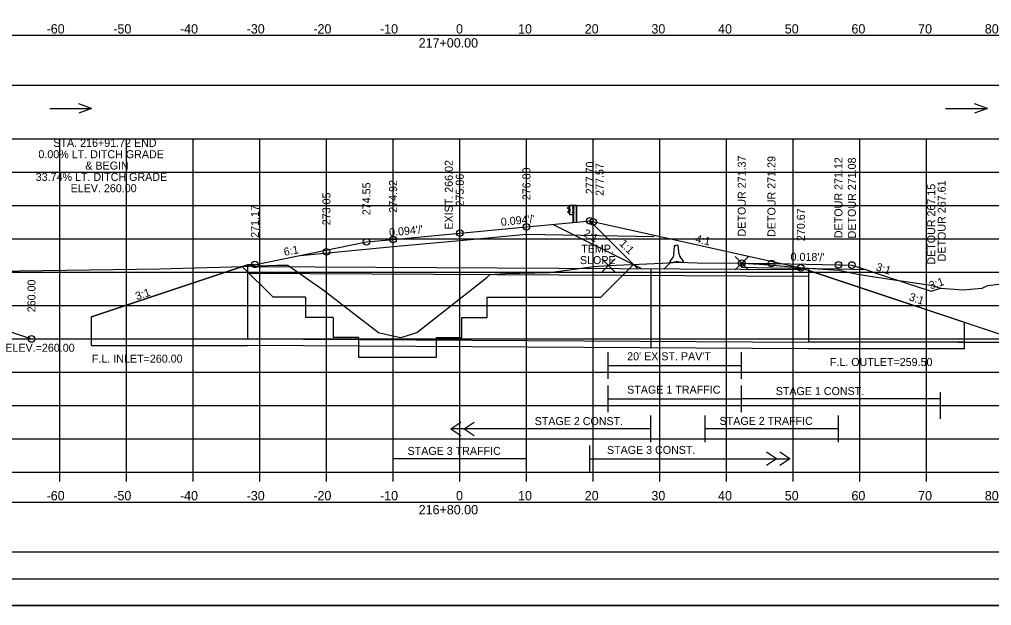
# Model space of a CAD drawing. Extents: x 4667 to 1632277, y -2100 to 724501.
# Drawn here: x 5711.1 to 5856.9, y -1323.8 to -1235.9 of the extents above; entities that cross this region are included whole.
import ezdxf

# ---------------------------------------------------------------- set-up
doc = ezdxf.new("R2010")
doc.units = 0
for name, color, linetype in [('R_Alt Surface', 7, 'Continuous'), ('R_Axis', 7, 'Continuous'), ('R_Axis Annot', 7, 'Continuous'), ('R_Border', 7, 'Continuous'), ('R_Border Notes', 7, 'Continuous'), ('R_Detour', 7, 'Continuous'), ('R_Detour Annot', 7, 'Continuous'), ('R_Draft', 7, 'Continuous'), ('R_Exist Surface', 7, 'Continuous'), ('R_Fin Surface', 7, 'Continuous'), ('R_Fin Surface Annot', 7, 'Continuous'), ('R_Grid', 7, 'Continuous'), ('R_MOT', 7, 'Continuous'), ('R_No Plot', 7, 'Continuous'), ('R_Proposed CofA', 7, 'Continuous'), ('R_ROW', 7, 'Continuous'), ('R_Striping', 7, 'Continuous'), ('R_Temp Easement', 7, 'Continuous'), ('R_Water', 7, 'Continuous'), ('R_Water Annot', 7, 'Continuous'), ('T_Drafting', 7, 'Continuous')]:
    doc.layers.add(name, color=color, linetype=linetype)

msp = doc.modelspace()

# ---------------------------------------------------------------- linework, layer by layer
at = {"layer": 'R_Alt Surface'}
msp.add_line((5805.83, -1273.23), (5805.83, -1285.1), dxfattribs=at)
msp.add_lwpolyline([(5753.27, -1271.24), (5767.18, -1269.93), (5777.18, -1268.99), (5787.18, -1268.05), (5806.34, -1268.43)], dxfattribs=at)
at = {"layer": 'R_Axis'}
for p, q in [((5667.18, -1303.77), (5947.18, -1303.77)), ((5717.18, -1305.17), (5717.18, -1303.77)), ((5727.18, -1305.17), (5727.18, -1303.77)), ((5737.18, -1305.17), (5737.18, -1303.77)), ((5747.18, -1305.17), (5747.18, -1303.77)), ((5757.18, -1305.17), (5757.18, -1303.77)), ((5767.18, -1305.17), (5767.18, -1303.77)), ((5777.18, -1305.17), (5777.18, -1303.77)), ((5787.18, -1305.17), (5787.18, -1303.77)), ((5797.18, -1305.17), (5797.18, -1303.77)), ((5807.18, -1305.17), (5807.18, -1303.77)), ((5817.18, -1305.17), (5817.18, -1303.77)), ((5827.18, -1305.17), (5827.18, -1303.77)), ((5837.18, -1305.17), (5837.18, -1303.77)), ((5847.18, -1305.17), (5847.18, -1303.77))]:
    msp.add_line(p, q, dxfattribs=at)
at = {"layer": 'R_Border'}
msp.add_line((5964.36, -1319.77), (5648.18, -1319.77), dxfattribs=at)
at = {"layer": 'R_Detour'}
msp.add_line((5847.89, -1276.62), (5849.29, -1276.15), dxfattribs=at)
for points in [[(5838.11, -1273.39), (5833.97, -1273.32), (5823.92, -1273.14), (5819.46, -1273.06), (5819.46, -1272.4)], [(5819.46, -1272.4), (5819.86, -1272.4), (5822.46, -1272.45), (5823.83, -1272.47), (5823.92, -1272.47), (5824.26, -1272.48), (5833.97, -1272.65), (5834.42, -1272.66), (5835.98, -1272.69), (5838.24, -1273.43), (5839.18, -1273.75), (5840.84, -1274.29), (5844.01, -1275.34), (5847.89, -1276.62)]]:
    msp.add_lwpolyline(points, dxfattribs=at)
at = {"layer": 'R_Draft'}
for p, q in [((5793.52, -1263.96), (5793.63, -1263.9)), ((5793.53, -1263.98), (5793.62, -1263.93)), ((5793.66, -1265.11), (5793.66, -1263.75)), ((5794.16, -1263.74), (5794.17, -1263.74)), ((5794.16, -1263.74), (5794.23, -1263.75)), ((5794.19, -1266.26), (5794.19, -1263.74)), ((5794.65, -1263.75), (5794.65, -1266.26)), ((5794.68, -1263.75), (5794.68, -1266.26)), ((5793.51, -1264.91), (5793.38, -1264.8)), ((5793.39, -1264.06), (5793.52, -1263.96)), ((5793.56, -1264.31), (5793.39, -1264.21)), ((5793.4, -1264.08), (5793.53, -1263.98)), ((5793.57, -1264.29), (5793.4, -1264.19)), ((5793.52, -1264.89), (5793.4, -1264.79)), ((5793.41, -1264.64), (5793.57, -1264.55)), ((5793.42, -1264.66), (5793.58, -1264.57)), ((5793.62, -1264.97), (5793.51, -1264.91)), ((5793.63, -1264.95), (5793.52, -1264.89)), ((5793.6, -1264.49), (5793.6, -1264.36)), ((5793.62, -1264.49), (5793.62, -1264.36)), ((5793.67, -1264.49), (5793.67, -1264.37)), ((5793.67, -1264.37), (5793.72, -1264.37)), ((5793.67, -1264.4), (5793.72, -1264.4)), ((5793.67, -1264.46), (5793.72, -1264.46)), ((5793.67, -1264.46), (5793.72, -1264.46)), ((5793.67, -1264.49), (5793.72, -1264.49)), ((5793.73, -1264.48), (5793.73, -1264.38)), ((5794.15, -1264.05), (5794.1, -1264.05)), ((5794.1, -1264.05), (5794.1, -1264.18)), ((5794.1, -1264.11), (5794.16, -1264.11)), ((5794.15, -1264.18), (5794.1, -1264.18)), ((5794.1, -1264.86), (5794.1, -1264.74)), ((5794.1, -1264.74), (5794.15, -1264.74)), ((5794.1, -1264.8), (5794.16, -1264.8)), ((5794.1, -1264.86), (5794.15, -1264.86)), ((5794.16, -1265.11), (5794.19, -1265.11)), ((5794.23, -1264.17), (5794.23, -1264.05)), ((5794.23, -1264.05), (5794.28, -1264.05)), ((5794.23, -1264.08), (5794.28, -1264.08)), ((5794.23, -1264.14), (5794.27, -1264.14)), ((5794.23, -1264.14), (5794.28, -1264.14)), ((5794.23, -1264.17), (5794.28, -1264.17)), ((5794.24, -1264.86), (5794.24, -1264.74)), ((5794.24, -1264.74), (5794.29, -1264.74)), ((5794.24, -1264.77), (5794.29, -1264.77)), ((5794.24, -1264.83), (5794.28, -1264.83)), ((5794.24, -1264.83), (5794.29, -1264.83)), ((5794.24, -1264.86), (5794.29, -1264.86)), ((5794.28, -1264.16), (5794.28, -1264.06)), ((5794.29, -1264.85), (5794.29, -1264.75))]:
    msp.add_line(p, q, dxfattribs=at)
for points in [[(5793.63, -1263.74), (5793.64, -1265.11), (5794.16, -1265.11), (5794.16, -1263.74)], [(5793.67, -1264.35), (5793.67, -1264.52), (5793.66, -1264.52), (5793.66, -1264.35)], [(5793.73, -1264.4), (5793.73, -1264.46), (5793.76, -1264.46), (5793.76, -1264.4)], [(5794.1, -1264.05), (5794.1, -1264.18), (5794.16, -1264.18), (5794.16, -1264.05)], [(5794.1, -1264.74), (5794.1, -1264.86), (5794.16, -1264.86), (5794.16, -1264.74)], [(5794.23, -1264.03), (5794.23, -1264.19), (5794.22, -1264.19), (5794.22, -1264.03)], [(5794.24, -1264.72), (5794.24, -1264.88), (5794.23, -1264.88), (5794.23, -1264.72)], [(5794.29, -1264.08), (5794.29, -1264.14), (5794.31, -1264.14), (5794.31, -1264.08)], [(5794.3, -1264.77), (5794.3, -1264.83), (5794.32, -1264.83), (5794.32, -1264.77)]]:
    msp.add_lwpolyline(points, close=True, dxfattribs=at)
msp.add_lwpolyline([(5794.68, -1263.75), (5794.23, -1263.75), (5794.23, -1266.26)], dxfattribs=at)
for centre, radius, start, end in [((5793.43, -1264.13), 0.0856, 122.0217, 240.7501), ((5793.47, -1264.74), 0.109, 120.88, 214.7816), ((5793.43, -1264.13), 0.062, 122.0217, 240.7501), ((5793.47, -1264.74), 0.0854, 120.88, 214.7816), ((5793.53, -1264.37), 0.0622, 4.9556, 61.894), ((5793.6, -1264.43), 0.0453, 93.9303, 257.0446), ((5793.53, -1264.37), 0.0865, 4.9556, 61.894), ((5793.55, -1264.5), 0.0462, 293.1464, 8.2196), ((5793.55, -1264.5), 0.0703, 293.1464, 8.2196), ((5793.71, -1264.38), 0.022, 317.7756, 45.4255), ((5793.64, -1264.43), 0.0922, 339.7423, 20.2577), ((5793.7, -1264.48), 0.025, 323.3766, 39.0666), ((5794.26, -1264.06), 0.022, 317.7756, 45.4255), ((5794.19, -1264.11), 0.0922, 339.7423, 20.2577), ((5794.26, -1264.16), 0.025, 323.3766, 39.0666), ((5794.27, -1264.75), 0.022, 317.7756, 45.4255), ((5794.2, -1264.8), 0.0922, 339.7423, 20.2577), ((5794.27, -1264.85), 0.025, 323.3766, 39.0666)]:
    msp.add_arc(centre, radius, start, end, dxfattribs=at)
at = {"layer": 'R_Exist Surface'}
msp.add_lwpolyline([(5693.57, -1273.8), (5732.18, -1273.26), (5733.86, -1273.21), (5742.97, -1272.97), (5749.72, -1272.7), (5751.4, -1272.69), (5756.7, -1276.4), (5764.98, -1282.78), (5766.89, -1283.26), (5768.33, -1283.53), (5769.98, -1283.04), (5770.75, -1282.8), (5781.22, -1274.57), (5781.72, -1274.1), (5783.99, -1273.95), (5790.64, -1273.82), (5797.3, -1272.92), (5797.99, -1272.85), (5799.47, -1272.78), (5807.54, -1272.42), (5809.96, -1272.27), (5812.79, -1272.34), (5819.46, -1272.4), (5822.13, -1272.55), (5823.49, -1272.66), (5829.32, -1273.18), (5834.02, -1273.45), (5837.11, -1274.09), (5841.33, -1274.74), (5847.83, -1275.69), (5849.32, -1276.17), (5852.6, -1276.41), (5855.53, -1276.17), (5856.38, -1275.76), (5862.08, -1275.08)], dxfattribs=at)
at = {"layer": 'R_Fin Surface'}
for points in [[(5683.37, -1273.91), (5712.95, -1283.77), (5721.97, -1283.77), (5721.97, -1280.44), (5745.35, -1272.64), (5746.35, -1272.64), (5763.18, -1269.22), (5767.18, -1268.85), (5777.18, -1267.91), (5787.18, -1266.97), (5794.68, -1266.26), (5796.68, -1266.07)], [(5851.85, -1284.27), (5861.84, -1284.27), (5896.84, -1284.27), (5928.43, -1273.74)]]:
    msp.add_lwpolyline(points, dxfattribs=at)
at = {"layer": 'R_Grid'}
for p, q in [((5667.18, -1253.77), (5947.18, -1253.77)), ((5717.18, -1303.77), (5717.18, -1253.77)), ((5727.18, -1303.77), (5727.18, -1253.77)), ((5737.18, -1303.77), (5737.18, -1253.77)), ((5747.18, -1303.77), (5747.18, -1253.77)), ((5757.18, -1303.77), (5757.18, -1253.77)), ((5767.18, -1303.77), (5767.18, -1253.77)), ((5777.18, -1303.77), (5777.18, -1253.77)), ((5787.18, -1303.77), (5787.18, -1253.77)), ((5797.18, -1303.77), (5797.18, -1253.77)), ((5807.18, -1303.77), (5807.18, -1253.77)), ((5817.18, -1303.77), (5817.18, -1253.77)), ((5827.18, -1303.77), (5827.18, -1253.77)), ((5837.18, -1303.77), (5837.18, -1253.77)), ((5847.18, -1303.77), (5847.18, -1253.77)), ((5667.18, -1258.77), (5947.18, -1258.77)), ((5667.18, -1263.77), (5947.18, -1263.77)), ((5667.18, -1268.77), (5947.18, -1268.77)), ((5667.18, -1273.77), (5947.18, -1273.77)), ((5667.18, -1278.77), (5947.18, -1278.77)), ((5667.18, -1283.77), (5947.18, -1283.77)), ((5667.18, -1288.77), (5947.18, -1288.77)), ((5667.18, -1293.77), (5947.18, -1293.77)), ((5667.18, -1298.77), (5947.18, -1298.77)), ((5667.18, -1303.77), (5947.18, -1303.77))]:
    msp.add_line(p, q, dxfattribs=at)
at = {"layer": 'R_MOT'}
for p, q in [((5809.46, -1269.74), (5809.65, -1269.74)), ((5809.84, -1269.73), (5809.65, -1269.74)), ((5809.3, -1271.12), (5809.4, -1269.8)), ((5810.08, -1271.09), (5809.91, -1269.78)), ((5808.72, -1272.18), (5809.16, -1271.51)), ((5808.73, -1272.35), (5808.72, -1272.18)), ((5809.23, -1272.33), (5808.73, -1272.35)), ((5809.72, -1272.15), (5809.23, -1272.33)), ((5810.23, -1272.3), (5809.72, -1272.15)), ((5810.73, -1272.29), (5810.23, -1272.3)), ((5810.72, -1272.12), (5810.24, -1271.48)), ((5810.73, -1272.29), (5810.72, -1272.12))]:
    msp.add_line(p, q, dxfattribs=at)
for centre, radius, start, end in [((5809.46, -1269.8), 0.0625, 91.6884, 175.6794), ((5809.85, -1269.79), 0.0625, 7.6974, 91.6884), ((5808.47, -1271.05), 0.833, 326.6964, 355.6794), ((5810.91, -1270.98), 0.833, 187.6974, 216.6804)]:
    msp.add_arc(centre, radius, start, end, dxfattribs=at)
at = {"layer": 'R_No Plot'}
for p, q in [((5791.18, -1266.59), (5804.45, -1273.22)), ((5635.78, -1323.75), (5969.12, -1323.75))]:
    msp.add_line(p, q, dxfattribs=at)
for points in [[(5635.78, -1110.41), (5969.12, -1110.41), (5969.12, -1323.75), (5635.78, -1323.75)], [(5882.1, -1114.31), (5901.72, -1114.31), (5901.72, -1124.19), (5917.84, -1124.19), (5941.04, -1124.19), (5941.04, -1148.52), (5964.36, -1148.52), (5964.36, -1319.77), (5648.18, -1319.77), (5648.18, -1114.31)]]:
    msp.add_lwpolyline(points, close=True, dxfattribs=at)
for points in [[(5799.47, -1272.78), (5798.47, -1271.78), (5799.47, -1272.78), (5798.47, -1273.78), (5799.47, -1272.78), (5800.47, -1273.78), (5799.47, -1272.78), (5800.47, -1271.78)], [(5819.46, -1272.4), (5818.46, -1271.4), (5819.46, -1272.4), (5818.46, -1273.4), (5819.46, -1272.4), (5820.46, -1273.4), (5819.46, -1272.4), (5820.46, -1271.4)]]:
    msp.add_lwpolyline(points, dxfattribs=at)
for centre in [(5787.18, -1266.97), (5796.68, -1266.07), (5797.18, -1266.2), (5777.18, -1267.91), (5763.18, -1269.22), (5767.18, -1268.85), (5757.18, -1270.72), (5746.46, -1272.6), (5819.46, -1272.4), (5823.92, -1272.47), (5828.33, -1273.1), (5833.97, -1272.65), (5835.98, -1272.69), (5712.95, -1283.77)]:
    msp.add_circle(centre, 0.5, dxfattribs=at)
at = {"layer": 'R_Proposed CofA'}
for p, q in [((5775.83, -1297.27), (5777.33, -1296.27)), ((5775.83, -1297.27), (5777.33, -1298.27)), ((5777.83, -1297.27), (5779.33, -1296.27)), ((5777.83, -1297.27), (5779.33, -1298.27)), ((5824.68, -1301.77), (5823.18, -1300.77)), ((5824.68, -1301.77), (5823.18, -1302.77)), ((5826.68, -1301.77), (5825.18, -1300.77)), ((5826.68, -1301.77), (5825.18, -1302.77))]:
    msp.add_line(p, q, dxfattribs=at)
for points in [[(5667.23, -1245.71), (5947.13, -1245.71), (5947.13, -1238.29), (5667.23, -1238.29)], [(5667.23, -1315.71), (5947.13, -1315.71), (5947.13, -1308.29), (5667.23, -1308.29)]]:
    msp.add_lwpolyline(points, close=True, dxfattribs=at)
at = {"layer": 'R_ROW'}
for p, q in [((5803.22, -1272.61), (5798.31, -1277.53)), ((5744.56, -1272.91), (5749.18, -1277.53)), ((5754.03, -1277.53), (5749.18, -1277.53)), ((5754.03, -1277.53), (5754.03, -1280.53)), ((5781.28, -1277.53), (5798.31, -1277.53)), ((5781.28, -1280.53), (5781.28, -1277.53)), ((5758.17, -1280.53), (5754.03, -1280.53)), ((5758.17, -1280.53), (5758.17, -1283.53)), ((5777.47, -1280.53), (5781.28, -1280.53)), ((5777.47, -1283.53), (5777.47, -1280.53)), ((5762.06, -1283.53), (5758.17, -1283.53)), ((5762.06, -1286.53), (5762.06, -1283.53)), ((5773.65, -1283.53), (5773.65, -1286.53)), ((5773.65, -1283.53), (5777.47, -1283.53)), ((5773.65, -1286.53), (5762.06, -1286.53))]:
    msp.add_line(p, q, dxfattribs=at)
at = {"layer": 'R_Striping'}
msp.add_lwpolyline([(5796.68, -1266.07), (5828.33, -1273.1), (5861.84, -1284.27)], dxfattribs=at)
at = {"layer": 'R_Temp Easement'}
for p, q in [((5799.42, -1289.77), (5799.42, -1285.77)), ((5819.42, -1289.77), (5819.42, -1285.77)), ((5799.42, -1287.77), (5819.42, -1287.77)), ((5799.42, -1294.77), (5799.42, -1290.77)), ((5819.42, -1294.77), (5819.42, -1290.77)), ((5799.42, -1292.77), (5819.42, -1292.77)), ((5849.29, -1292.77), (5819.46, -1292.77)), ((5849.29, -1295.77), (5849.29, -1291.77)), ((5805.83, -1299.27), (5805.83, -1295.27)), ((5813.98, -1299.27), (5813.98, -1295.27)), ((5833.98, -1299.27), (5833.98, -1295.27)), ((5805.83, -1297.27), (5775.83, -1297.27)), ((5833.98, -1297.27), (5813.98, -1297.27)), ((5767.18, -1303.77), (5767.18, -1299.77)), ((5787.18, -1303.77), (5787.18, -1299.77)), ((5796.68, -1303.77), (5796.68, -1299.77)), ((5787.18, -1301.77), (5767.18, -1301.77)), ((5796.68, -1301.77), (5826.68, -1301.77))]:
    msp.add_line(p, q, dxfattribs=at)
at = {"layer": 'R_Water'}
for p, q in [((5745.35, -1272.64), (5721.97, -1280.44)), ((5745.35, -1273.77), (5745.35, -1283.77)), ((5745.35, -1273.89), (5829.47, -1274.35)), ((5746.35, -1272.89), (5828.47, -1273.34)), ((5829.47, -1273.48), (5852.85, -1281.27)), ((5829.47, -1274.27), (5829.47, -1284.27)), ((5721.97, -1284.73), (5721.97, -1280.44)), ((5852.85, -1285.23), (5852.85, -1281.27)), ((5721.97, -1283.77), (5745.35, -1283.77)), ((5745.35, -1283.77), (5829.47, -1284.27)), ((5852.85, -1284.27), (5829.47, -1284.27)), ((5721.97, -1284.73), (5745.35, -1284.73)), ((5829.47, -1285.23), (5745.35, -1284.73)), ((5852.85, -1285.23), (5829.47, -1285.23))]:
    msp.add_line(p, q, dxfattribs=at)
for points in [[(5746.35, -1272.89), (5746.35, -1272.64), (5745.35, -1272.64), (5745.35, -1273.77)], [(5828.47, -1273.34), (5828.47, -1273.14), (5829.47, -1273.14), (5829.47, -1274.27)]]:
    msp.add_lwpolyline(points, dxfattribs=at)
at = {"layer": 'R_Water Annot'}
for p, q in [((5715.69, -1249.2), (5721.97, -1249.2)), ((5721.97, -1249.2), (5720.05, -1248.5)), ((5721.97, -1249.2), (5720.05, -1249.9)), ((5850.02, -1249.2), (5856.3, -1249.2)), ((5856.3, -1249.2), (5854.38, -1248.5)), ((5856.3, -1249.2), (5854.38, -1249.9))]:
    msp.add_line(p, q, dxfattribs=at)
at = {"layer": 'T_Drafting'}
for p, q in [((5796.68, -1266.07), (5803.83, -1273.22)), ((5807.83, -1273.24), (5808.73, -1272.35)), ((5803.83, -1273.22), (5807.83, -1273.24))]:
    msp.add_line(p, q, dxfattribs=at)

# ---------------------------------------------------------------- texts
at = {"layer": 'R_Alt Surface'}
msp.add_text('1:1', height=1.2, rotation=315, dxfattribs=at).set_placement((5801.03, -1269.57))
at = {"layer": 'R_Axis Annot'}
for s, p in [('-60', (5715.22, -1237.97)), ('-50', (5725.22, -1237.97)), ('-40', (5735.22, -1237.97)), ('-30', (5745.22, -1237.97)), ('-20', (5755.22, -1237.97)), ('-10', (5765.22, -1237.97)), ('0', (5776.62, -1237.97)), ('10', (5785.92, -1237.97)), ('20', (5795.92, -1237.97)), ('30', (5805.92, -1237.97)), ('40', (5815.92, -1237.97)), ('50', (5825.92, -1237.97)), ('60', (5835.92, -1237.97)), ('70', (5845.92, -1237.97)), ('80', (5855.92, -1237.97)), ('217+00.00', (5771.02, -1240.07)), ('-60', (5715.22, -1307.97)), ('-50', (5725.22, -1307.97)), ('-40', (5735.22, -1307.97)), ('-30', (5745.22, -1307.97)), ('-20', (5755.22, -1307.97)), ('-10', (5765.22, -1307.97)), ('0', (5776.62, -1307.97)), ('10', (5785.92, -1307.97)), ('20', (5795.92, -1307.97)), ('30', (5805.92, -1307.97)), ('40', (5815.92, -1307.97)), ('50', (5825.92, -1307.97)), ('60', (5835.92, -1307.97)), ('70', (5845.92, -1307.97)), ('80', (5855.92, -1307.97)), ('216+80.00', (5771.02, -1310.07))]:
    msp.add_text(s, height=1.4, dxfattribs=at).set_placement(p)
at = {"layer": 'R_Border Notes'}
for s, p in [('TEMP.', (5795.4, -1270.85)), ('SLOPE', (5795.2, -1272.55))]:
    msp.add_text(s, height=1.2, dxfattribs=at).set_placement(p)
at = {"layer": 'R_Detour'}
msp.add_text('3:1', height=1.2, rotation=18.7248, dxfattribs=at).set_placement((5847.8, -1276.36))
at = {"layer": 'R_Detour Annot'}
for s, rotation, p in [("0.018'/'", 358.9828, (5826.78, -1272.03)), ('3:1', 341.7516, (5839.48, -1273.45))]:
    msp.add_text(s, height=1.2, rotation=rotation, dxfattribs=at).set_placement(p)
at = {"layer": 'R_Fin Surface Annot'}
for s, rotation, p in [('DETOUR 271.37', 90, (5820.06, -1268.4)), ('DETOUR 271.29', 90, (5824.52, -1268.47)), ('DETOUR 271.12', 90, (5834.57, -1268.65)), ('DETOUR 271.08', 90, (5836.58, -1268.69)), ('277.70', 90, (5797.28, -1262.07)), ('277.57', 90, (5798.75, -1262.31)), ('275.86', 90, (5777.78, -1263.91)), ('276.80', 90, (5787.78, -1262.97)), ('274.55', 90, (5763.78, -1265.22)), ('274.92', 90, (5767.78, -1264.85)), ('DETOUR 267.15', 90, (5848.48, -1272.63)), ('DETOUR 267.61', 90, (5850.05, -1272.14)), ('273.05', 90, (5757.78, -1266.72)), ('271.17', 90, (5747.06, -1268.6)), ("0.094'/'", 5.37, (5783.39, -1266.82)), ('270.67', 90, (5828.93, -1269.1)), ("0.094'/'", 5.37, (5766.64, -1268.39)), ('4:1', 347.5089, (5812.44, -1269.28)), ('6:1', 9.9301, (5750.89, -1271.32)), ('260.00', 90, (5713.55, -1279.77)), ('3:1', 18.4349, (5728.76, -1277.97)), ('3:1', 341.5651, (5844.46, -1277.95))]:
    msp.add_text(s, height=1.2, rotation=rotation, dxfattribs=at).set_placement(p)
at = {"layer": 'R_No Plot'}
msp.add_text('2:1', height=1.2, rotation=330.9929, dxfattribs=at).set_placement((5795.57, -1268.25))
at = {"layer": 'R_Temp Easement'}
msp.add_text('EXIST. 266.02', height=1.2, rotation=90, dxfattribs=at).set_placement((5776.13, -1267.38))
for s, height, p in [("20' EXIST. PAV'T", 1.2, (5802.28, -1286.97)), ('STAGE 1 TRAFFIC', 1.2, (5802.28, -1291.97)), ('STAGE 1 CONST.', 1.1985, (5824.56, -1292.19)), ('STAGE 2 CONST.', 1.1985, (5788.41, -1296.69)), ('STAGE 2 TRAFFIC', 1.1985, (5816.14, -1296.66)), ('STAGE 3 TRAFFIC', 1.1985, (5769.35, -1301.16)), ('STAGE 3 CONST.', 1.1985, (5799.25, -1301.01))]:
    msp.add_text(s, height=height, dxfattribs=at).set_placement(p)
at = {"layer": 'R_Water Annot'}
for s, p in [('STA. 216+91.72 END', (5716.23, -1254.97)), ('0.00% LT. DITCH GRADE', (5713.99, -1256.67)), ('& BEGIN', (5721.02, -1258.37)), ('33.74% LT. DITCH GRADE', (5713.59, -1260.07)), ('ELEV. 260.00', (5718.82, -1261.77)), ('ELEV.=260.00', (5709.03, -1285.69)), ('F.L. INLET=260.00', (5722.01, -1287.33)), ('F.L. OUTLET=259.50', (5832.68, -1287.83))]:
    msp.add_text(s, height=1.2, dxfattribs=at).set_placement(p)

doc.saveas('drawing.dxf')
